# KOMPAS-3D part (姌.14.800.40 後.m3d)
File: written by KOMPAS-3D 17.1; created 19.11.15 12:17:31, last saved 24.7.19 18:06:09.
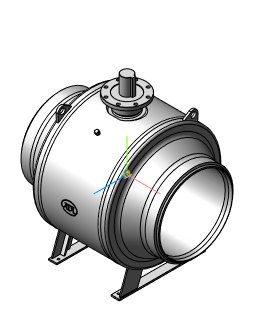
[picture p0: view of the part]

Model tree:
1. Операция без истории:3  (labels: Сталь 20  ГОСТ 1050-88)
